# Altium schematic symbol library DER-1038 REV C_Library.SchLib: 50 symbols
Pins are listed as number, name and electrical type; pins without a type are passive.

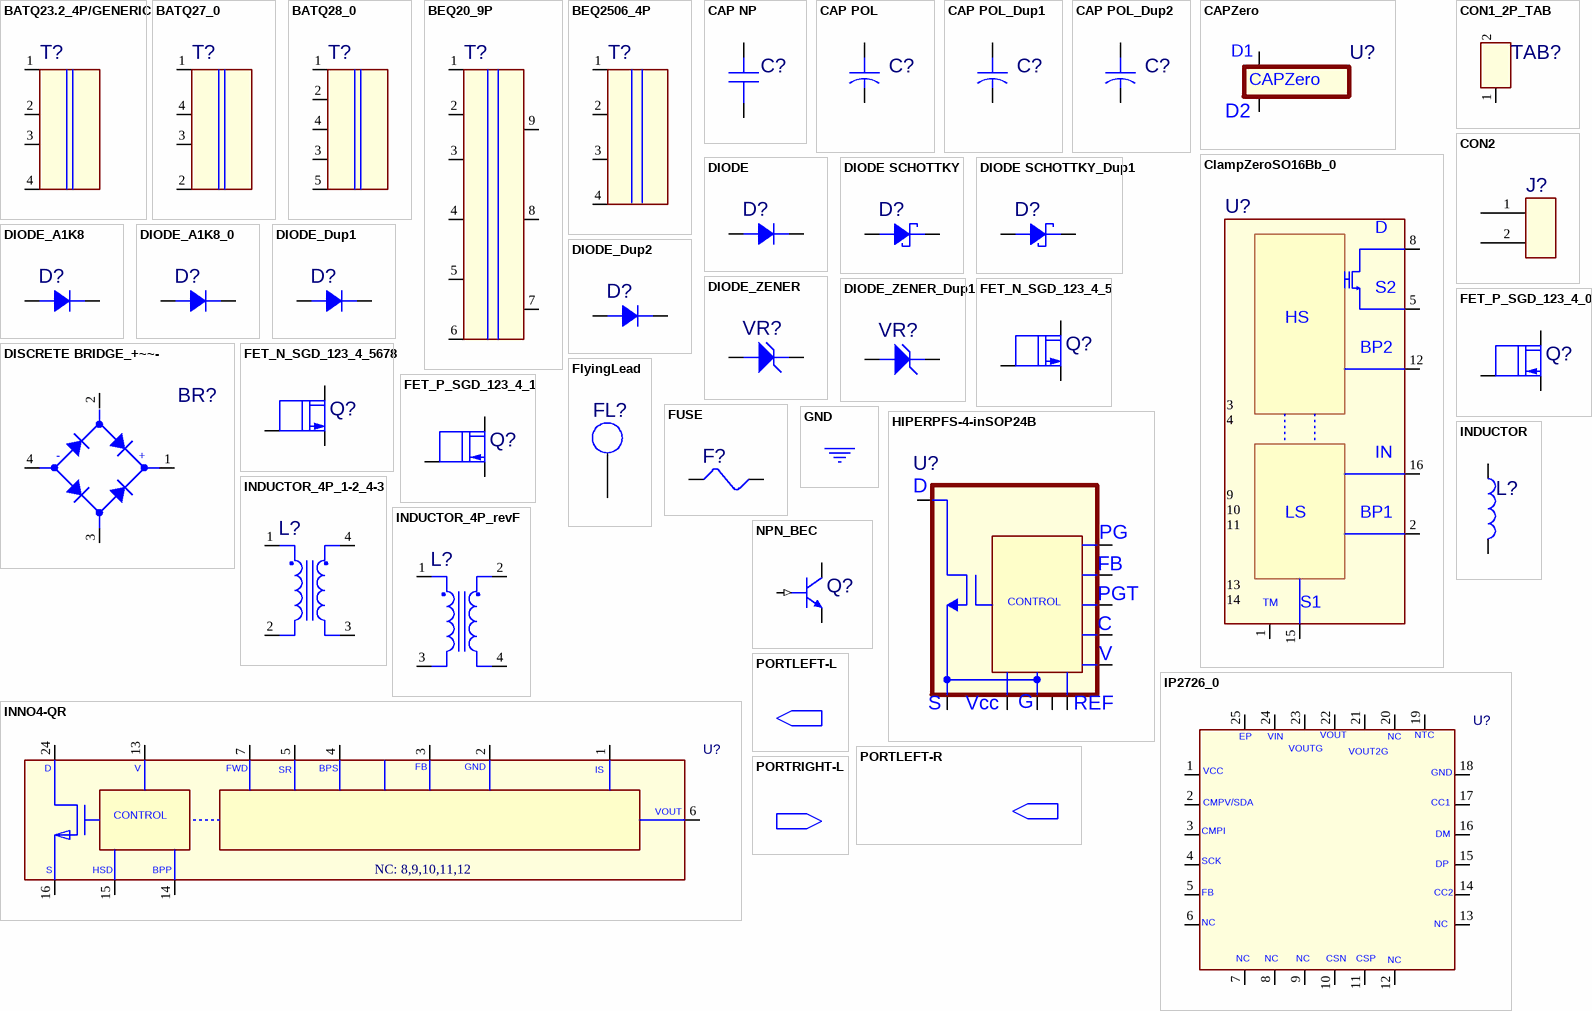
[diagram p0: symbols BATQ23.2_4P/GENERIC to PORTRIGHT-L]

## BATQ23.2_4P/GENERIC
designator T?
pins: 1, 2, 3, 4

## BATQ27_0
designator T?
pins: 1, 2, 3, 4

## BATQ28_0
designator T?
pins: 1, 2, 3, 4, 5

## BEQ20_9P
designator T?
pins: 1, 2, 3, 4, 5, 6, 7, 8, 9

## BEQ2506_4P
designator T?
pins: 1, 2, 3, 4

## CAP NP
designator C?
footprint RAD/.250X.125/LS.200/.031
pins: 1, 2

## CAP POL
designator C?
pins: 1, 2

## CAP POL_Dup1
designator C?
pins: 1, 2

## CAP POL_Dup2
designator C?
pins: 1, 2

## CAPZero
designator U?
pins: 1 NC1, 2 D1, 3 NC2, 4 NC3, 5 NC4, 6 NC5, 7 D2, 8 NC8

## ClampZeroSO16Bb_0
designator U?
PACK_SHORT: (S2,S9,S10,S11)
pins: 1 TRIM, 2 BP1, 3 NC3, 4 NC4, 5 S2, 8 D, 9 S9, 10 S10, 11 S11, 12 BP2, 13 NC13, 14 NC14, 15 S1, 16 IN

## CON1_2P_TAB
designator TAB?  (value not drawn)
PACK_SHORT: (1,2)
pins: 1, 2

## CON2
designator J?  (value not drawn)
pins: 1, 2

## DIODE
designator D?
pins: 1, 2

## DIODE SCHOTTKY
designator D?
footprint DAX1/.500X.225/.062
pins: 1, 2

## DIODE SCHOTTKY_Dup1
designator D?
footprint DAX1/.500X.225/.062
pins: 1, 2

## DIODE_A1K8
designator D?
pins: 1 A, 8 K

## DIODE_A1K8_0
designator D?
pins: 1 A, 8 K

## DIODE_Dup1
designator D?
pins: 1, 2

## DIODE_Dup2
designator D?
pins: 1, 2

## DIODE_ZENER
designator VR?
footprint DIO/W.80/LS.400/.030
pins: 1, 2

## DIODE_ZENER_Dup1
designator VR?
footprint DIO/W.80/LS.400/.030
pins: 1, 2

## DISCRETE BRIDGE_+~~-
designator BR?
pins: 1 +DC, 2 AC1, 3 AC2, 4 -DC

## FET_N_SGD_123_4_5
designator Q?
PACK_SHORT: (S,S2,S3)
pins: 1 S, 2 S2, 3 S3, 4 G, 5 D

## FET_N_SGD_123_4_5678
designator Q?
PACK_SHORT: (S,S2,S3)(D,D6,D7,D8)
pins: 1 S, 2 S2, 3 S3, 4 G, 5 D, 6 D6, 7 D7, 8 D8

## FET_P_SGD_123_4_0
designator Q?
PACK_SHORT: (S,S2,S3)(D,D6,D7,D8)
pins: 1 S, 2 S2, 3 S3, 4 G, 5 D, 6 D6, 7 D7, 8 D8

## FET_P_SGD_123_4_1
designator Q?
PACK_SHORT: (S,S2,S3)(D,D6,D7,D8)
pins: 1 S, 2 S2, 3 S3, 4 G, 5 D, 6 D6, 7 D7, 8 D8

## FlyingLead
designator FL?  (value not drawn)
pins: 1

## FUSE
designator F?
pins: 1, 2

## GND
designator *  (value not drawn)  (graphical)
pins: $PIN0 (power) hidden to $PIN0

## HIPERPFS-4-inSOP24B
designator U?
NC: 9,10,11,13,14,15; PACK_SHORT: (G,G12)
pins: 1 VCC, 2 G, 3 REF, 4 V, 5 C, 6 FB, 7 PG, 8 PGT, 12 G12, 16 D, 24 S

## INDUCTOR
designator L?
pins: 1, 2

## INDUCTOR_4P_1-2_4-3
designator L?
pins: 1, 2, 3, 4

## INDUCTOR_4P_revF
designator L?
pins: 1, 2, 3, 4

## INNO4-QR
designator U?  NC: 8,9,10,11,12
pins: 1, 2, 3, 4, 5, 6, 7, 13, 14, 15, 16, 24

## IP2726_0
designator U?
pins: 1, 2, 3, 4, 5, 6, 7, 8, 9, 10, 11, 12, 13, 14, 15, 16, 17, 18, 19, 20, 21, 22, 23, 24, 25

## NPN_BEC
designator Q?
pins: 1 BASE (in), 2 EMITTER, 3 COLLECTOR

## PORTLEFT-L
designator *  (value not drawn)  (graphical)
pins: PORTLEFT-L (out)

## PORTLEFT-R
designator *  (value not drawn)  (graphical)
pins: PORTLEFT-R (out)

## PORTRIGHT-L
designator *  (value not drawn)  (graphical)
pins: PORTRIGHT-L (in)

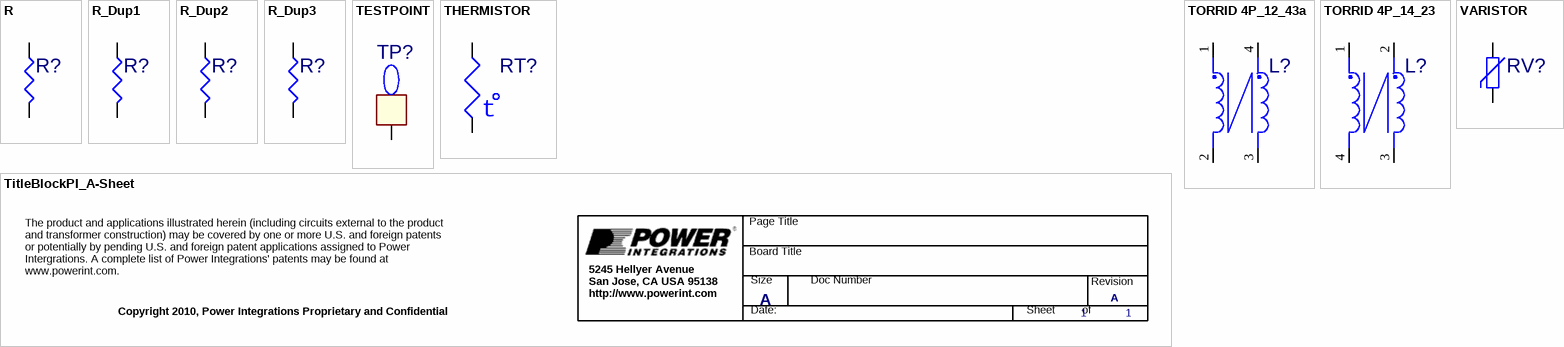
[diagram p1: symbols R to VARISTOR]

## R
designator R?
pins: 1, 2

## R_Dup1
designator R?
pins: 1, 2

## R_Dup2
designator R?
pins: 1, 2

## R_Dup3
designator R?
pins: 1, 2

## TESTPOINT
designator TP?  (value not drawn)
pins: 1

## THERMISTOR
designator RT?
pins: 1, 2

## TitleBlockPI_A-Sheet
designator *  Page Size: A  Page Number: 1  (hidden comment: *)  (graphical)

## TORRID 4P_12_43a
designator L?
pins: 1, 2, 3, 4

## TORRID 4P_14_23
designator L?
pins: 1, 2, 3, 4

## VARISTOR
designator RV?
pins: 1, 2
